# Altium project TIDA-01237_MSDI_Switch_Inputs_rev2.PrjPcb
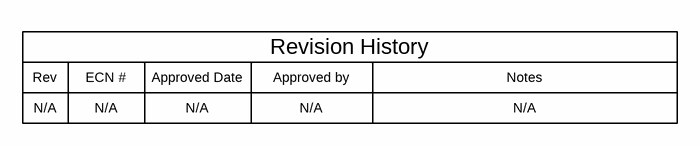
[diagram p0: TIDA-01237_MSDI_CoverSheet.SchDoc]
TID: TIDA-01237; TechSupport: http://www.ti.com/support; SCH_Rev: E2; PRJ_Title: MSDI Switch Inputs TI Design; PRJ_Number: TIDA-01237; PRJ_Engineer: John Griffith; PRJ_Customer: Public Release; PCB_Rev: E2; PCB_Layout: John Griffith; CopyrightYear: 2016
5 sheets, 162 parts. Net scope: global (net labels, ports and power ports of the same name join across sheets).
Board file: TIDA-01237_MSDI_Switch_Inputs_PCB_Rev2.PcbDoc
Sheets:
  TIDA-01237_MSDI_CoverSheet.SchDoc
  TIDA-01237_MSDI_Main.SchDoc
  TIDA-01237_MSDI_Matrix_Inputs.SchDoc
  TIDA-01237_MSDI_Resistor_Coded_Inputs.SchDoc
  TIDA-01237_MSDI_Hardware.SchDoc

## Sheet TIDA-01237_MSDI_CoverSheet.SchDoc
size 431 x 279 mm; Date: Not shown in title block; ApprovedBy: Not shown in title block; CheckedBy: Not shown in title block; Author: Not shown in title block; CompanyName: Not shown in title block; Engineer: Not shown in title block; Organization: Not shown in title block; Address1: Not shown in title block; Address2: Not shown in title block; Address3: Not shown in title block; Address4: Not shown in title block; DocumentNumber: 1; Revision: Use project parameter SCH_Rev; SheetNumber: 1; SheetTotal: 5; PageSetup: Record=PageOptions¦CenterHorizontal=True¦CenterVertical=True¦PrintScale=1.00¦XCorrection=1.00¦YCorrection=1.00¦PrintKind=0¦BorderSize=5000000¦LeftOffset=0¦BottomOffset=0¦Orientation=2¦PaperLength=1000¦PaperWidth=1000¦Scale=100¦PaperSource=15¦PrintQuality=600¦MediaType=1¦DitherType=10¦PaperKind=Letter¦PrintScaleMode=1

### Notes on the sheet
- Rev
- N/A
- ECN #
- Approved Date
- Approved by
- Revision History
- Notes

## Sheet TIDA-01237_MSDI_Main.SchDoc
size 431 x 279 mm; Date: Not shown in title block; ApprovedBy: Not shown in title block; CheckedBy: Not shown in title block; Author: Not shown in title block; CompanyName: Not shown in title block; DrawnBy: John Griffith; Engineer: Not shown in title block; Organization: Not shown in title block; Address1: Not shown in title block; Address2: Not shown in title block; Address3: Not shown in title block; Address4: Not shown in title block; DocumentNumber: 1; Revision: Use project parameter SCH_Rev; SheetNumber: 2; SheetTotal: 5; PageSetup: Record=PageOptions¦CenterHorizontal=True¦CenterVertical=True¦PrintScale=0.64¦XCorrection=1.00¦YCorrection=1.00¦PrintKind=0¦BorderSize=5000000¦LeftOffset=0¦BottomOffset=0¦Orientation=2¦PaperLength=1000¦PaperWidth=1000¦Scale=100¦PaperSource=15¦PrintQuality=600¦MediaType=1¦DitherType=10¦PrintScaleMode=1¦PaperKind=Letter
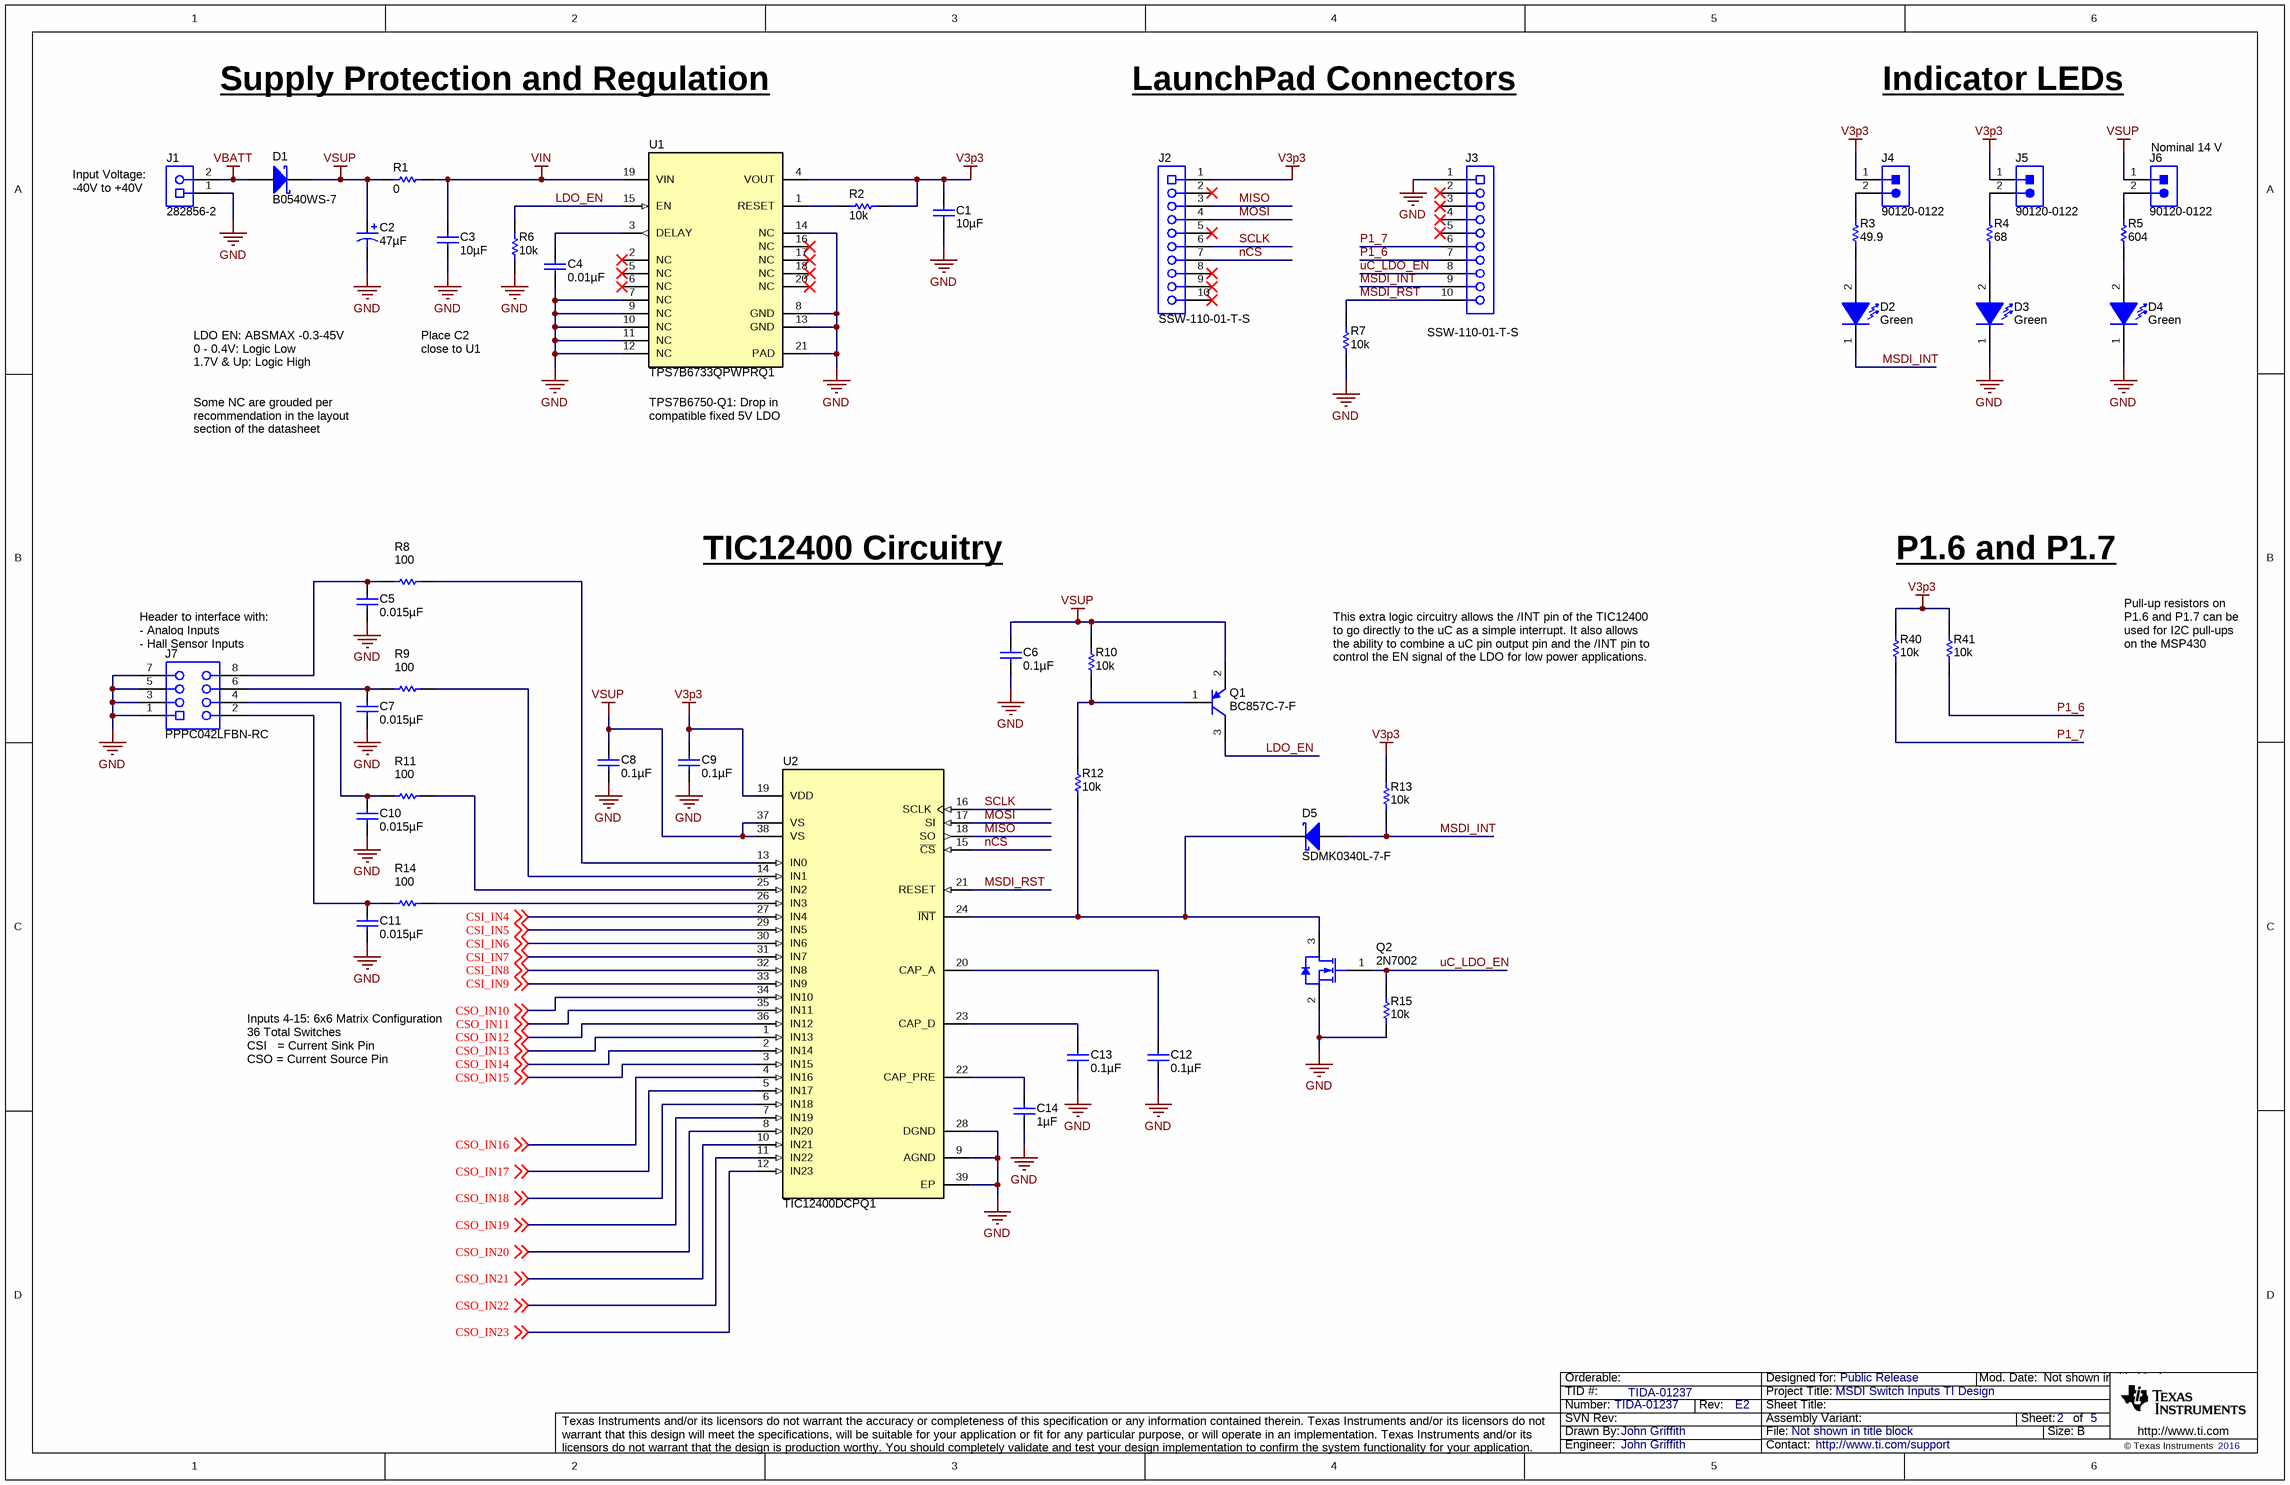
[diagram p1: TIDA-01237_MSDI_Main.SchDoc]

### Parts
C1  ValueDisplayed: 10µF  [0603S]  (hidden comment: C1608X5R1A106M080AC)
C2  ValueDisplayed: 47µF  [CAPSMT_62_F80]  (hidden comment: EMVE500ADA470MF80G)
C3  ValueDisplayed: 10µF  [1210_280]  (hidden comment: C3225X7R1H106M250AC)
C4  ValueDisplayed: 0.01µF  [0603S]  (hidden comment: C0603C103J5RACTU)
C5  ValueDisplayed: 0.015µF  [0603S]  (hidden comment: C0603C153J3GACTU)
C6  ValueDisplayed: 0.1µF  [0603S]  (hidden comment: 0603YC104JAT2A)
C7  ValueDisplayed: 0.015µF  [0603S]  (hidden comment: C0603C153J3GACTU)
C8  ValueDisplayed: 0.1µF  [0603S]  (hidden comment: 06035C104KAT2A)
C9  ValueDisplayed: 0.1µF  [0603S]  (hidden comment: 0603YC104JAT2A)
C10  ValueDisplayed: 0.015µF  [0603S]  (hidden comment: C0603C153J3GACTU)
C11  ValueDisplayed: 0.015µF  [0603S]  (hidden comment: C0603C153J3GACTU)
C12  ValueDisplayed: 0.1µF  [0603S]  (hidden comment: C1608X7R1E104K080AA)
C13  ValueDisplayed: 0.1µF  [0603S]  (hidden comment: C1608X7R1E104K080AA)
C14  ValueDisplayed: 1µF  [0603S]  (hidden comment: C1608X7R1C105K080AC)
D1  B0540WS-7  [SOD-323]
D2  value Green  [WL-SMCW_GREEN]  (hidden comment: 150060VS75000)
D3  value Green  [WL-SMCW_GREEN]  (hidden comment: 150060VS75000)
D4  value Green  [WL-SMCW_GREEN]  (hidden comment: 150060VS75000)
D5  SDMK0340L-7-F  [SOD-323]
J1  282856-2  [TE_282856-2]
J2  SSW-110-01-T-S  [Samtec_SSW-110-x1-x-S]
J3  SSW-110-01-T-S  [Samtec_SSW-110-x1-x-S]
J4  90120-0122  [CONN_90120-0122]
J5  90120-0122  [CONN_90120-0122]
J6  90120-0122  [CONN_90120-0122]
J7  PPPC042LFBN-RC  [CONN_PPPC042LFBN-RC]
Q1  BC857C-7-F  [SOT-23]
Q2  2N7002  [SOT-23]
R1  ValueDisplayed: 0  [5106]  (hidden comment: 5106)
R2  ValueDisplayed: 10k  [0603S]  (hidden comment: CRCW060310K0JNEA)
R3  ValueDisplayed: 49.9  [0402]  (hidden comment: ERJ-2RKF49R9X)
R4  ValueDisplayed: 68  [0402]  (hidden comment: CRCW040268R0JNED)
R5  ValueDisplayed: 604  [0402]  (hidden comment: CRCW0402604RFKED)
R6  ValueDisplayed: 10k  [0603S]  (hidden comment: CRCW060310K0JNEA)
R7  ValueDisplayed: 10k  [0603S]  (hidden comment: CRCW060310K0JNEA)
R8  ValueDisplayed: 100  [0603S]  (hidden comment: CRCW0603100RFKEA)
R9  ValueDisplayed: 100  [0603S]  (hidden comment: CRCW0603100RFKEA)
R10  ValueDisplayed: 10k  [0603S]  (hidden comment: CRCW060310K0JNEA)
R11  ValueDisplayed: 100  [0603S]  (hidden comment: CRCW0603100RFKEA)
R12  ValueDisplayed: 10k  [0603S]  (hidden comment: CRCW060310K0JNEA)
R13  ValueDisplayed: 10k  [0603S]  (hidden comment: CRCW060310K0JNEA)
R14  ValueDisplayed: 100  [0603S]  (hidden comment: CRCW0603100RFKEA)
R15  ValueDisplayed: 10k  [0603S]  (hidden comment: CRCW060310K0JNEA)
R40  ValueDisplayed: 10k  [0603S]  (hidden comment: RC0603JR-0710KL)
R41  ValueDisplayed: 10k  [0603S]  (hidden comment: RC0603JR-0710KL)
U1  TPS7B6733QPWPRQ1  [PWP0020D_N]
U2  TIC12400DCPQ1  [DCP0038A_N]

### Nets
GND: C1.2 C2.2(-) C3.2 C4.2 C5.2 C6.2 C7.2 C8.2 C9.2 C10.2 C11.2 C12.2 C13.2 C14.2 D3.1(K) D4.1(K) J1.1 J3.1 J7.1 J7.3 J7.5 J7.7 Q2.2(S) R6.1 R7.1 R15.2 U1.7(NC) U1.8(GND) U1.9(NC) U1.10(NC) U1.11(NC) U1.12(NC) U1.13(GND) U1.14(NC) U1.21(PAD) U2.9(AGND) U2.28(DGND) U2.39(EP)
V3p3: C1.1 C9.1 J2.1 J4.1 J5.1 R2.2 R13.2 R40.2 R41.2 U1.4(VOUT) U2.19(VDD)
VBATT: D1.2(A) J1.2
VIN: C3.1 R1.2 U1.19(VIN)
VSUP: C2.1(+) C6.1 C8.1 D1.1(K) J6.1 Q1.2(E) R1.1 R10.2 U2.37(VS) U2.38(VS)
CSI_IN4: U2.27(IN4) ; off-sheet CSI_IN4
CSI_IN5: U2.29(IN5) ; off-sheet CSI_IN5
CSI_IN6: U2.30(IN6) ; off-sheet CSI_IN6
CSI_IN7: U2.31(IN7) ; off-sheet CSI_IN7
CSI_IN8: U2.32(IN8) ; off-sheet CSI_IN8
CSI_IN9: U2.33(IN9) ; off-sheet CSI_IN9
CSO_IN10: U2.34(IN10) ; off-sheet CSO_IN10
CSO_IN11: U2.35(IN11) ; off-sheet CSO_IN11
CSO_IN12: U2.36(IN12) ; off-sheet CSO_IN12
CSO_IN13: U2.1(IN13) ; off-sheet CSO_IN13
CSO_IN14: U2.2(IN14) ; off-sheet CSO_IN14
CSO_IN15: U2.3(IN15) ; off-sheet CSO_IN15
CSO_IN16: U2.4(IN16) ; off-sheet CSO_IN16
CSO_IN17: U2.5(IN17) ; off-sheet CSO_IN17
CSO_IN18: U2.6(IN18) ; off-sheet CSO_IN18
CSO_IN19: U2.7(IN19) ; off-sheet CSO_IN19
CSO_IN20: U2.8(IN20) ; off-sheet CSO_IN20
CSO_IN21: U2.10(IN21) ; off-sheet CSO_IN21
CSO_IN22: U2.11(IN22) ; off-sheet CSO_IN22
CSO_IN23: U2.12(IN23) ; off-sheet CSO_IN23
LDO_EN: Q1.3(C) R6.2 U1.15(EN)
MISO: J2.3 U2.18(SO)
MOSI: J2.4 U2.17(SI)
MSDI_INT: D2.1(K) D5.2(A) J3.9 R13.1
MSDI_RST: J3.10 R7.2 U2.21(RESET)
nCS: J2.7 U2.15(~{CS})
P1_6: J3.7 R41.1
P1_7: J3.6 R40.1
SCLK: J2.6 U2.16(SCLK)
uC_LDO_EN: J3.8 Q2.1(G) R15.1
NetC4_1: C4.1 U1.3(DELAY)
NetC5_1: C5.1 J7.8 R8.1
NetC7_1: C7.1 J7.6 R9.1
NetC10_1: C10.1 J7.4 R11.1
NetC11_1: C11.1 J7.2 R14.1
NetC12_1: C12.1 U2.20(CAP_A)
NetC13_1: C13.1 U2.23(CAP_D)
NetC14_1: C14.1 U2.22(CAP_PRE)
NetD2_2: D2.2(A) R3.1
NetD3_2: D3.2(A) R4.1
NetD4_2: D4.2(A) R5.1
NetD5_1: D5.1(K) Q2.3(D) R12.2 U2.24(~{INT})
NetJ4_2: J4.2 R3.2
NetJ5_2: J5.2 R4.2
NetJ6_2: J6.2 R5.2
NetQ1_1: Q1.1(B) R10.1 R12.1
NetR2_1: R2.1 U1.1(RESET)
NetR8_2: R8.2 U2.13(IN0)
NetR9_2: R9.2 U2.14(IN1)
NetR11_2: R11.2 U2.25(IN2)
NetR14_2: R14.2 U2.26(IN3)

Not connected (* = marked no-connect by the designer): J2 2* 5* 8* 9* 10*; J3 2* 3* 4* 5*; U1 2(NC)* 5(NC)* 6(NC)* 16(NC)* 17(NC)* 18(NC)* 20(NC)*

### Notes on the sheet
- Supply Protection and Regulation
- LaunchPad Connectors
- Indicator LEDs
- (near J6) Nominal 14 V
- (near J1) Input Voltage:
  -40V to +40V
- LDO EN: ABSMAX -0.3-45V
  0 - 0.4V: Logic Low
  1.7V & Up: Logic High
- Place C2 close to U1
- Some NC are grouded per recommendation in the layout section of the datasheet
- (near U1) TPS7B6750-Q1: Drop in compatible fixed 5V LDO
- (near J7) - Analog Inputs
- Header to interface with:
- TIC12400 Circuitry
- P1.6 and P1.7
- (near J7) - Hall Sensor Inputs
- This extra logic circuitry allows the /INT pin of the TIC12400 to go directly to the uC as a simple interrupt. It also allows the ability to combine a uC pin output pin and the /INT pin to control the EN signal of the LDO for low power applications.
- Pull-up resistors on P1.6 and P1.7 can be used for I2C pull-ups on the MSP430
- Inputs 4-15: 6x6 Matrix Configuration
  36 Total Switches
  CSI   = Current Sink Pin
  CSO = Current Source Pin

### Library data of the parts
C1 = C1608X5R1A106M080AC: CAP, CERM, 10 µF, 10 V, +/- 20%, X5R, 0603; Manufacturer: TDK; Polarized: N; CompType: Capacitor; Value: 10uF; U/M: EA; Cap_F: 0.00001; Tolerance_%: 20; ESR_ohm: 0.0078; Value1: 0.0078 ohm; VDC_V: 10; Value2: 10V; IRMS_A: 1.85; TaMin_C: -55; TaMax_C: 85; Cap_Case: 0603; SizeArea_mm2: 1.28; SizeAreaWB_mm2: 4.68; SizeX_mm: 1.6; SizeY_mm: 0.8; SizeZ_mm: 1; AEC Category: Q200
C2 = EMVE500ADA470MF80G: CAP, AL, 47 µF, 50 V, +/- 20%, SMD; Manufacturer: Chemi-Con; Polarized: Y; CompType: Capacitor; Value: 47uF; U/M: EA; Cap_F: 0.000047; Tolerance_%: 20; Value1: Unknown; VDC_V: 50; Value2: 50V; IRMS_A: 0.08; TaMin_C: -40; TaMax_C: 105; Cap_Case: F80; SizeAreaWB_mm2: 73.96; SizeArea_mm2: 43.56; SizeX_mm: 6.6; SizeZ_mm: 7.7; AEC Category: Q200
C3 = C3225X7R1H106M250AC: CAP, CERM, 10 µF, 50 V, +/- 20%, X7R, 1210; Manufacturer: TDK; Polarized: N; CompType: Capacitor; Value: 10uF; U/M: EA; Cap_F: 0.00001; Tolerance_%: 20; Value1: Unknown; VDC_V: 50; Value2: 50V; TaMin_C: -55; TaMax_C: 125; Cap_Case: 1210; SizeArea_mm2: 8; SizeAreaWB_mm2: 14.7; SizeX_mm: 3.2; SizeY_mm: 2.5; SizeZ_mm: 2.8; AEC Category: Q200
C4 = C0603C103J5RACTU: CAP, CERM, 0.01 µF, 50 V, +/- 5%, X7R, 0603; Manufacturer: Kemet; Polarized: N; CompType: Capacitor; Value: 0.01uF; U/M: EA; Cap_F: 0.00000001; Tolerance_%: 5; Value1: Unknown; VDC_V: 50; Value2: 50V; TaMin_C: -55; TaMax_C: 125; Cap_Case: 0603; SizeArea_mm2: 1.28; SizeAreaWB_mm2: 4.68; SizeX_mm: 1.6; SizeY_mm: 0.8; SizeZ_mm: 1; AEC Category: Q200
C5 C7 C10 C11 = C0603C153J3GACTU: CAP, CERM, 0.015 µF, 25 V, +/- 5%, C0G/NP0, 0603; Manufacturer: Kemet; Polarized: N; CompType: Capacitor; Value: 0.015uF; U/M: EA; Cap_F: 0.000000015; Tolerance_%: 5; Value1: Unknown; VDC_V: 25; Value2: 25V; TaMin_C: -55; TaMax_C: 125; Cap_Case: 0603; SizeArea_mm2: 1.28; SizeAreaWB_mm2: 4.68; SizeX_mm: 1.6; SizeY_mm: 0.8; SizeZ_mm: 1; AEC Category: Q200
C6 C9 = 0603YC104JAT2A: CAP, CERM, 0.1 µF, 16 V, +/- 5%, X7R, 0603; Manufacturer: AVX; Polarized: N; CompType: Capacitor; Value: 0.1uF; U/M: EA; Cap_F: 0.0000001; Tolerance_%: 5; ESR_ohm: 0.039; Value1: 0.039 ohm; VDC_V: 16; Value2: 16V; TaMin_C: -55; TaMax_C: 125; Cap_Case: 0603; SizeArea_mm2: 1.28; SizeAreaWB_mm2: 4.68; SizeX_mm: 1.6; SizeY_mm: 0.8; SizeZ_mm: 1; AEC Category: Q200
C8 = 06035C104KAT2A: CAP, CERM, 0.1 µF, 50 V, +/- 10%, X7R, 0603; Manufacturer: AVX; Polarized: N; CompType: Capacitor; Value: 0.1uF; U/M: EA; Cap_F: 0.0000001; Tolerance_%: 10; Value1: Unknown; VDC_V: 50; Value2: 50V; TaMin_C: -55; TaMax_C: 125; Cap_Case: 0603; SizeArea_mm2: 1.28; SizeAreaWB_mm2: 4.68; SizeX_mm: 1.6; SizeY_mm: 0.8; SizeZ_mm: 1; AEC Category: Q200
C12 C13 = C1608X7R1E104K080AA: CAP, CERM, 0.1 µF, 25 V, +/- 10%, X7R, 0603; Manufacturer: TDK; Polarized: N; CompType: Capacitor; Value: 0.1uF; U/M: EA; Cap_F: 0.0000001; Tolerance_%: 10; Value1: Unknown; VDC_V: 25; Value2: 25V; TaMin_C: -55; TaMax_C: 125; Cap_Case: 0603; SizeArea_mm2: 1.28; SizeAreaWB_mm2: 4.68; SizeX_mm: 1.6; SizeY_mm: 0.8; SizeZ_mm: 1; AEC Category: Q200
C14 = C1608X7R1C105K080AC: CAP, CERM, 1 µF, 16 V, +/- 10%, X7R, 0603; Manufacturer: TDK; Polarized: N; CompType: Capacitor; Value: 1uF; U/M: EA; Cap_F: 0.000001; Tolerance_%: 10; ESR_ohm: 0.0057; Value1: 0.0057 ohm; VDC_V: 16; Value2: 16V; TaMin_C: -55; TaMax_C: 125; Cap_Case: 0603; SizeArea_mm2: 1.28; SizeAreaWB_mm2: 4.68; SizeX_mm: 1.6; SizeY_mm: 0.8; SizeZ_mm: 1; AEC Category: Q200
D1 = B0540WS-7: Diode, Schottky, 40 V, 0.5 A, SOD-323; Manufacturer: Diodes Inc.; U/M: EA; Vf_V: 0.55; Value: 40V; Value1: 0.5A; Value2: 0.55V; Io_A: 0.5; Vr_V: 40; TJmax_C: 125; SizeAreaWB_mm2: 8.695; SizeArea_mm2: 3.645; SizeX_mm: 2.7; SizeY_mm: 1.35; SizeZ_mm: 1; AEC Category: Q101
D2-D4 = 150060VS75000: LED, Green, SMD; Manufacturer: Wurth Elektronik; Type: AlInGaP; Vf_V: 2; Value2: 2V; Io_A: 0.02; Value1: W; U/M: EA
D5 = SDMK0340L-7-F: Diode, Schottky, 40 V, 0.03 A, SOD-323; Manufacturer: Diodes Inc.; U/M: EA; Vf_V: 1; Value: 40V; Value1: 0.03A; Value2: 1V; Io_A: 0.03; Vr_V: 40; SizeAreaWB_mm2: 8.695; SizeArea_mm2: 3.645; SizeX_mm: 2.7; SizeY_mm: 1.35; AEC Category: Q101
J1 = 282856-2: Therminal Block, 5 mm, 2-pole, Tin, TH; Manufacturer: TE Connectivity; SymbolCreator: a0412235; CompType: Terminal Block
J2 J3 = SSW-110-01-T-S: Receptacle, 2.54mm, 10x1, Tin, TH; Manufacturer: Samtec; SymbolCreator: a0411947; Pitch_mm: 2.54; Gender: Female; Row_Count: 1; Cert_CSA: Y
J4-J6 = 90120-0122: Header, 100mil, 2x1, Tin, TH; Manufacturer: Molex; SymbolCreator: a0412235
J7 = PPPC042LFBN-RC: Connector, Receptacle, 100mil, 4x2, Gold plated, TH; Manufacturer: Sullins Connector Solutions; SymbolCreator: a0412235
Q1 = BC857C-7-F, Diodes Inc.: Transistor, PNP, 45 V, 0.1 A, SOT-23; CompType: BJT; PNP: 1; NPN: 0; Vceo_V: 45; Vcesat1_V: 0.075; Value: 45 V; IcRated_A: 0.1; Value1: 0.1 A; HfeMax: 600; TaMin_C: -65; TaMax_C: 150; U/M: EA; AEC Category: Q101
Q2 = 2N7002: MOSFET, N-CH, 60 V, 115 A, SOT-23; Manufacturer: Fairchild Semiconductor; Alternate Manufacturer: None; U/M: EA; ChType: N; Value: 60V; VdsMax_V: 60; Value1: ? ohm; Value2: ? nC; Vgs_V: 20; IdsMax_A: 115; SizeAreaWB_mm2: 14; SizeArea_mm2: 7.5; SizeX_mm: 2.5; SizeY_mm: 3; SizeZ_mm: 1.1; AEC Category: Q101
R1 = 5106: RES, 0, 1%, 0.5 W, 0805; Manufacturer: Keystone; CompType: Resistor; Value: 0; Tolerance_%: 1; Power_W: 0.5; Value2: 0.5W; TempCo: ppm/C; SizeArea_mm2: 2.5; SizeX_mm: 2; SizeY_mm: 1.25; SizeZ_mm: 0.84; U/M: EA; AEC Category: Q200; AEC Qualified: N
R2 R6 R7 R10 R12 R13 R15 = CRCW060310K0JNEA: RES, 10 k, 5%, 0.1 W, 0603; Manufacturer: Vishay-Dale; CompType: Resistor; Value: 10k; Res_ohm: 10000; Value_Code: 10k0; Tolerance_%: 5; Power_W: 0.1; Value2: 0.1W; VDC_V: 75; TempCo: 200 ppm/C; SizeArea_mm2: 1.28; SizeX_mm: 1.6; SizeY_mm: 0.8; SizeZ_mm: 1; EIA_Code: E24; U/M: EA; AEC Category: Q200
R3 = ERJ-2RKF49R9X: RES, 49.9, 1%, 0.1 W, AEC-Q200 Grade 0, 0402; Manufacturer: Panasonic; CompType: Resistor; Value: 49.9; Value_Code: 49R9; Tolerance_%: 1; Power_W: 0.1; Value2: 0.1W; VDC_V: 50; TempCo: 100 ppm/C; SizeArea_mm2: 0.5; SizeZ_mm: 0.6; EIA_Code: E96; U/M: EA; AEC Category: Q200; AEC Qualified: Y; AEC Grade: 0
R4 = CRCW040268R0JNED: RES, 68, 5%, 0.063 W, 0402; Manufacturer: Vishay-Dale; CompType: Resistor; Value: 68; Value_Code: 68R0; Tolerance_%: 5; Power_W: 0.063; Value2: 0.063W; VDC_V: 50; TempCo: 200 ppm/C; SizeArea_mm2: 0.5; SizeX_mm: 1; SizeZ_mm: 0.6; EIA_Code: E24; U/M: EA; AEC Category: Q200
R5 = CRCW0402604RFKED: RES, 604, 1%, 0.063 W, 0402; Manufacturer: Vishay-Dale; CompType: Resistor; Value: 604; Value_Code: 604R; Tolerance_%: 1; Power_W: 0.063; Value2: 0.063W; VDC_V: 50; TempCo: 100 ppm/C; SizeArea_mm2: 0.5; SizeZ_mm: 0.6; EIA_Code: E96; U/M: EA; AEC Category: Q200
R8 R9 R11 R14 = CRCW0603100RFKEA: RES, 100, 1%, 0.1 W, 0603; Manufacturer: Vishay-Dale; CompType: Resistor; Value: 100; Value_Code: 100R; Tolerance_%: 1; Power_W: 0.1; Value2: 0.1W; VDC_V: 75; TempCo: 100 ppm/C; SizeArea_mm2: 1.28; SizeX_mm: 1.6; SizeY_mm: 0.8; EIA_Code: E96; U/M: EA; AEC Category: Q200
R40 R41 = RC0603JR-0710KL: RES, 10 k, 5%, 0.1 W, 0603; Manufacturer: Yageo America; CompType: Resistor; Value: 10k; Res_ohm: 10000; Value_Code: 10k0; Tolerance_%: 5; Power_W: 0.1; Value2: 0.1W; VDC_V: 50; TempCo: 100 ppm/C; SizeArea_mm2: 1.28; SizeX_mm: 1.6; SizeY_mm: 0.8; SizeZ_mm: 1; EIA_Code: E24; U/M: EA; AEC Category: Q200
U1 = TPS7B6733QPWPRQ1: 450-mA High-Voltage Ultra-Low IQ Low-Dropout Regulator, PWP0020D; Manufacturer: Texas Instruments; SymbolCreator: Altium; SizeArea_mm2: 41.6; SizeAreaWB_mm2: 71.4; SizeX_mm: 6.4; SizeY_mm: 6.5; SizeZ_mm: 1.2; CompType: IC; U/M: EA
U2 = TIC12400DCPQ1: Multiple Switch Detection Interface (MSDI) device, DCP0038A; Manufacturer: Texas Instruments; SymbolCreator: Altium; SizeArea_mm2: 62.08; SizeAreaWB_mm2: 98.28; SizeX_mm: 6.4; SizeY_mm: 9.7; SizeZ_mm: 1.2; CompType: IC; U/M: EA

## Sheet TIDA-01237_MSDI_Matrix_Inputs.SchDoc
size 431 x 279 mm; Date: Not shown in title block; ApprovedBy: Not shown in title block; CheckedBy: Not shown in title block; Author: Not shown in title block; CompanyName: Not shown in title block; Engineer: Not shown in title block; Organization: Not shown in title block; Address1: Not shown in title block; Address2: Not shown in title block; Address3: Not shown in title block; Address4: Not shown in title block; DocumentNumber: 1; Revision: Use project parameter SCH_Rev; SheetNumber: 3; SheetTotal: 5; PageSetup: Record=PageOptions¦CenterHorizontal=True¦CenterVertical=True¦PrintScale=1.00¦XCorrection=1.00¦YCorrection=1.00¦PrintKind=0¦BorderSize=5000000¦LeftOffset=0¦BottomOffset=0¦Orientation=2¦PaperLength=1000¦PaperWidth=1000¦Scale=100¦PaperSource=15¦PrintQuality=600¦MediaType=1¦DitherType=10¦PaperKind=Letter¦PrintScaleMode=1
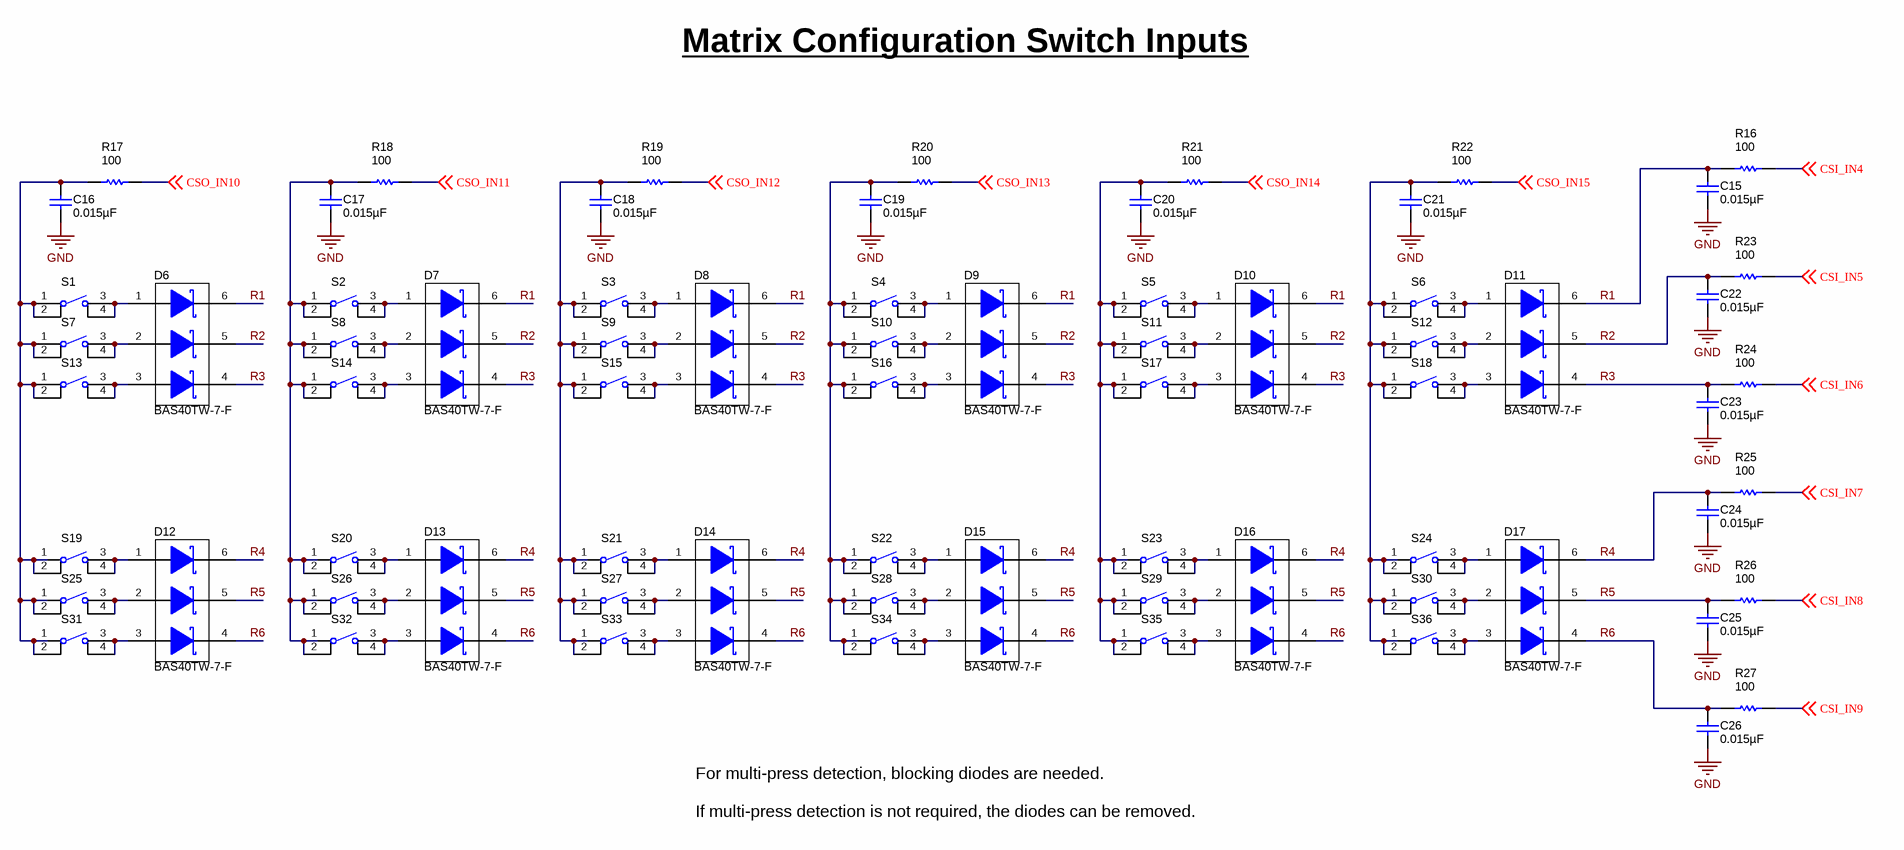
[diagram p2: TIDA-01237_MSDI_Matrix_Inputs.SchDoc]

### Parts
C15  ValueDisplayed: 0.015µF  [0603S]  (hidden comment: C0603C153J3GACTU)
C16  ValueDisplayed: 0.015µF  [0603S]  (hidden comment: C0603C153J3GACTU)
C17  ValueDisplayed: 0.015µF  [0603S]  (hidden comment: C0603C153J3GACTU)
C18  ValueDisplayed: 0.015µF  [0603S]  (hidden comment: C0603C153J3GACTU)
C19  ValueDisplayed: 0.015µF  [0603S]  (hidden comment: C0603C153J3GACTU)
C20  ValueDisplayed: 0.015µF  [0603S]  (hidden comment: C0603C153J3GACTU)
C21  ValueDisplayed: 0.015µF  [0603S]  (hidden comment: C0603C153J3GACTU)
C22  ValueDisplayed: 0.015µF  [0603S]  (hidden comment: C0603C153J3GACTU)
C23  ValueDisplayed: 0.015µF  [0603S]  (hidden comment: C0603C153J3GACTU)
C24  ValueDisplayed: 0.015µF  [0603S]  (hidden comment: C0603C153J3GACTU)
C25  ValueDisplayed: 0.015µF  [0603S]  (hidden comment: C0603C153J3GACTU)
C26  ValueDisplayed: 0.015µF  [0603S]  (hidden comment: C0603C153J3GACTU)
D6  BAS40TW-7-F  [SOT-363]
D7  BAS40TW-7-F  [SOT-363]
D8  BAS40TW-7-F  [SOT-363]
D9  BAS40TW-7-F  [SOT-363]
D10  BAS40TW-7-F  [SOT-363]
D11  BAS40TW-7-F  [SOT-363]
D12  BAS40TW-7-F  [SOT-363]
D13  BAS40TW-7-F  [SOT-363]
D14  BAS40TW-7-F  [SOT-363]
D15  BAS40TW-7-F  [SOT-363]
D16  BAS40TW-7-F  [SOT-363]
D17  BAS40TW-7-F  [SOT-363]
R16  ValueDisplayed: 100  [0603S]  (hidden comment: CRCW0603100RFKEA)
R17  ValueDisplayed: 100  [0603S]  (hidden comment: CRCW0603100RFKEA)
R18  ValueDisplayed: 100  [0603S]  (hidden comment: CRCW0603100RFKEA)
R19  ValueDisplayed: 100  [0603S]  (hidden comment: CRCW0603100RFKEA)
R20  ValueDisplayed: 100  [0603S]  (hidden comment: CRCW0603100RFKEA)
R21  ValueDisplayed: 100  [0603S]  (hidden comment: CRCW0603100RFKEA)
R22  ValueDisplayed: 100  [0603S]  (hidden comment: CRCW0603100RFKEA)
R23  ValueDisplayed: 100  [0603S]  (hidden comment: CRCW0603100RFKEA)
R24  ValueDisplayed: 100  [0603S]  (hidden comment: CRCW0603100RFKEA)
R25  ValueDisplayed: 100  [0603S]  (hidden comment: CRCW0603100RFKEA)
R26  ValueDisplayed: 100  [0603S]  (hidden comment: CRCW0603100RFKEA)
R27  ValueDisplayed: 100  [0603S]  (hidden comment: CRCW0603100RFKEA)
S1  4-1437565-1  [SW_FSM4JSMA]  (value not drawn)
S2  4-1437565-1  [SW_FSM4JSMA]  (value not drawn)
S3  4-1437565-1  [SW_FSM4JSMA]  (value not drawn)
S4  4-1437565-1  [SW_FSM4JSMA]  (value not drawn)
S5  4-1437565-1  [SW_FSM4JSMA]  (value not drawn)
S6  4-1437565-1  [SW_FSM4JSMA]  (value not drawn)
S7  4-1437565-1  [SW_FSM4JSMA]  (value not drawn)
S8  4-1437565-1  [SW_FSM4JSMA]  (value not drawn)
S9  4-1437565-1  [SW_FSM4JSMA]  (value not drawn)
S10  4-1437565-1  [SW_FSM4JSMA]  (value not drawn)
S11  4-1437565-1  [SW_FSM4JSMA]  (value not drawn)
S12  4-1437565-1  [SW_FSM4JSMA]  (value not drawn)
S13  4-1437565-1  [SW_FSM4JSMA]  (value not drawn)
S14  4-1437565-1  [SW_FSM4JSMA]  (value not drawn)
S15  4-1437565-1  [SW_FSM4JSMA]  (value not drawn)
S16  4-1437565-1  [SW_FSM4JSMA]  (value not drawn)
S17  4-1437565-1  [SW_FSM4JSMA]  (value not drawn)
S18  4-1437565-1  [SW_FSM4JSMA]  (value not drawn)
S19  4-1437565-1  [SW_FSM4JSMA]  (value not drawn)
S20  4-1437565-1  [SW_FSM4JSMA]  (value not drawn)
S21  4-1437565-1  [SW_FSM4JSMA]  (value not drawn)
S22  4-1437565-1  [SW_FSM4JSMA]  (value not drawn)
S23  4-1437565-1  [SW_FSM4JSMA]  (value not drawn)
S24  4-1437565-1  [SW_FSM4JSMA]  (value not drawn)
S25  4-1437565-1  [SW_FSM4JSMA]  (value not drawn)
S26  4-1437565-1  [SW_FSM4JSMA]  (value not drawn)
S27  4-1437565-1  [SW_FSM4JSMA]  (value not drawn)
S28  4-1437565-1  [SW_FSM4JSMA]  (value not drawn)
S29  4-1437565-1  [SW_FSM4JSMA]  (value not drawn)
S30  4-1437565-1  [SW_FSM4JSMA]  (value not drawn)
S31  4-1437565-1  [SW_FSM4JSMA]  (value not drawn)
S32  4-1437565-1  [SW_FSM4JSMA]  (value not drawn)
S33  4-1437565-1  [SW_FSM4JSMA]  (value not drawn)
S34  4-1437565-1  [SW_FSM4JSMA]  (value not drawn)
S35  4-1437565-1  [SW_FSM4JSMA]  (value not drawn)
S36  4-1437565-1  [SW_FSM4JSMA]  (value not drawn)

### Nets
GND: C15.2 C16.2 C17.2 C18.2 C19.2 C20.2 C21.2 C22.2 C23.2 C24.2 C25.2 C26.2
CSI_IN4: R16.2 ; off-sheet CSI_IN4
CSI_IN5: R23.2 ; off-sheet CSI_IN5
CSI_IN6: R24.2 ; off-sheet CSI_IN6
CSI_IN7: R25.2 ; off-sheet CSI_IN7
CSI_IN8: R26.2 ; off-sheet CSI_IN8
CSI_IN9: R27.2 ; off-sheet CSI_IN9
CSO_IN10: R17.2 ; off-sheet CSO_IN10
CSO_IN11: R18.2 ; off-sheet CSO_IN11
CSO_IN12: R19.2 ; off-sheet CSO_IN12
CSO_IN13: R20.2 ; off-sheet CSO_IN13
CSO_IN14: R21.2 ; off-sheet CSO_IN14
CSO_IN15: R22.2 ; off-sheet CSO_IN15
R1: C15.1 D6.6(C) D7.6(C) D8.6(C) D9.6(C) D10.6(C) D11.6(C) R16.1
R2: C22.1 D6.5(NC) D7.5(NC) D8.5(NC) D9.5(NC) D10.5(NC) D11.5(NC) R23.1
R3: C23.1 D6.4(C) D7.4(C) D8.4(C) D9.4(C) D10.4(C) D11.4(C) R24.1
R4: C24.1 D12.6(C) D13.6(C) D14.6(C) D15.6(C) D16.6(C) D17.6(C) R25.1
R5: C25.1 D12.5(NC) D13.5(NC) D14.5(NC) D15.5(NC) D16.5(NC) D17.5(NC) R26.1
R6: C26.1 D12.4(C) D13.4(C) D14.4(C) D15.4(C) D16.4(C) D17.4(C) R27.1
NetC16_1: C16.1 R17.1 S1.1 S1.2 S7.1 S7.2 S13.1 S13.2 S19.1 S19.2 S25.1 S25.2 S31.1 S31.2
NetC17_1: C17.1 R18.1 S2.1 S2.2 S8.1 S8.2 S14.1 S14.2 S20.1 S20.2 S26.1 S26.2 S32.1 S32.2
NetC18_1: C18.1 R19.1 S3.1 S3.2 S9.1 S9.2 S15.1 S15.2 S21.1 S21.2 S27.1 S27.2 S33.1 S33.2
NetC19_1: C19.1 R20.1 S4.1 S4.2 S10.1 S10.2 S16.1 S16.2 S22.1 S22.2 S28.1 S28.2 S34.1 S34.2
NetC20_1: C20.1 R21.1 S5.1 S5.2 S11.1 S11.2 S17.1 S17.2 S23.1 S23.2 S29.1 S29.2 S35.1 S35.2
NetC21_1: C21.1 R22.1 S6.1 S6.2 S12.1 S12.2 S18.1 S18.2 S24.1 S24.2 S30.1 S30.2 S36.1 S36.2
NetD6_1: D6.1(A) S1.3 S1.4
NetD6_2: D6.2(NC) S7.3 S7.4
NetD6_3: D6.3(A) S13.3 S13.4
NetD7_1: D7.1(A) S2.3 S2.4
NetD7_2: D7.2(NC) S8.3 S8.4
NetD7_3: D7.3(A) S14.3 S14.4
NetD8_1: D8.1(A) S3.3 S3.4
NetD8_2: D8.2(NC) S9.3 S9.4
NetD8_3: D8.3(A) S15.3 S15.4
NetD9_1: D9.1(A) S4.3 S4.4
NetD9_2: D9.2(NC) S10.3 S10.4
NetD9_3: D9.3(A) S16.3 S16.4
NetD10_1: D10.1(A) S5.3 S5.4
NetD10_2: D10.2(NC) S11.3 S11.4
NetD10_3: D10.3(A) S17.3 S17.4
NetD11_1: D11.1(A) S6.3 S6.4
NetD11_2: D11.2(NC) S12.3 S12.4
NetD11_3: D11.3(A) S18.3 S18.4
NetD12_1: D12.1(A) S19.3 S19.4
NetD12_2: D12.2(NC) S25.3 S25.4
NetD12_3: D12.3(A) S31.3 S31.4
NetD13_1: D13.1(A) S20.3 S20.4
NetD13_2: D13.2(NC) S26.3 S26.4
NetD13_3: D13.3(A) S32.3 S32.4
NetD14_1: D14.1(A) S21.3 S21.4
NetD14_2: D14.2(NC) S27.3 S27.4
NetD14_3: D14.3(A) S33.3 S33.4
NetD15_1: D15.1(A) S22.3 S22.4
NetD15_2: D15.2(NC) S28.3 S28.4
NetD15_3: D15.3(A) S34.3 S34.4
NetD16_1: D16.1(A) S23.3 S23.4
NetD16_2: D16.2(NC) S29.3 S29.4
NetD16_3: D16.3(A) S35.3 S35.4
NetD17_1: D17.1(A) S24.3 S24.4
NetD17_2: D17.2(NC) S30.3 S30.4
NetD17_3: D17.3(A) S36.3 S36.4

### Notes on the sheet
- Matrix Configuration Switch Inputs
- For multi-press detection, blocking diodes are needed.
  If multi-press detection is not required, the diodes can be removed.

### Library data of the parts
C15-C26 = C0603C153J3GACTU: as C5 on sheet TIDA-01237_MSDI_Main
D6-D17 = BAS40TW-7-F: Diode, Schottky, 40 V, 0.2 A, AEC-Q101, SOT-363; Manufacturer: Diodes Inc.; SymbolCreator: Altium; U/M: EA; Vf_V: 1; Value: 40V; Value1: 0.2A; Value2: 1V; Io_A: 0.2; Vr_V: 40; TJmax_C: 125; SizeAreaWB_mm2: 10.24; SizeArea_mm2: 4.84; SizeX_mm: 2.2; SizeZ_mm: 1.1; AEC Category: Q101; AEC Qualified: Y
R16-R27 = CRCW0603100RFKEA: as R8 on sheet TIDA-01237_MSDI_Main
S1-S36 = 4-1437565-1: Switch, Tactile, SPST-NO, 0.05A, 12V, SMT; Manufacturer: TE Connectivity; SymbolCreator: a0412235; VDC_V: 12; SwitchFunction: Off-Mom; PositionCount: 1; CurrentRating_mA: 50

## Sheet TIDA-01237_MSDI_Resistor_Coded_Inputs.SchDoc
size 431 x 279 mm; Date: Not shown in title block; ApprovedBy: Not shown in title block; CheckedBy: Not shown in title block; Author: Not shown in title block; CompanyName: Not shown in title block; Engineer: Not shown in title block; Organization: Not shown in title block; Address1: Not shown in title block; Address2: Not shown in title block; Address3: Not shown in title block; Address4: Not shown in title block; DocumentNumber: 1; Revision: Use project parameter SCH_Rev; SheetNumber: 4; SheetTotal: 5; PageSetup: Record=PageOptions¦CenterHorizontal=True¦CenterVertical=True¦PrintScale=1.00¦XCorrection=1.00¦YCorrection=1.00¦PrintKind=0¦BorderSize=5000000¦LeftOffset=0¦BottomOffset=0¦Orientation=2¦PaperLength=1000¦PaperWidth=1000¦Scale=100¦PaperSource=15¦PrintQuality=600¦MediaType=1¦DitherType=10¦PaperKind=Letter¦PrintScaleMode=1
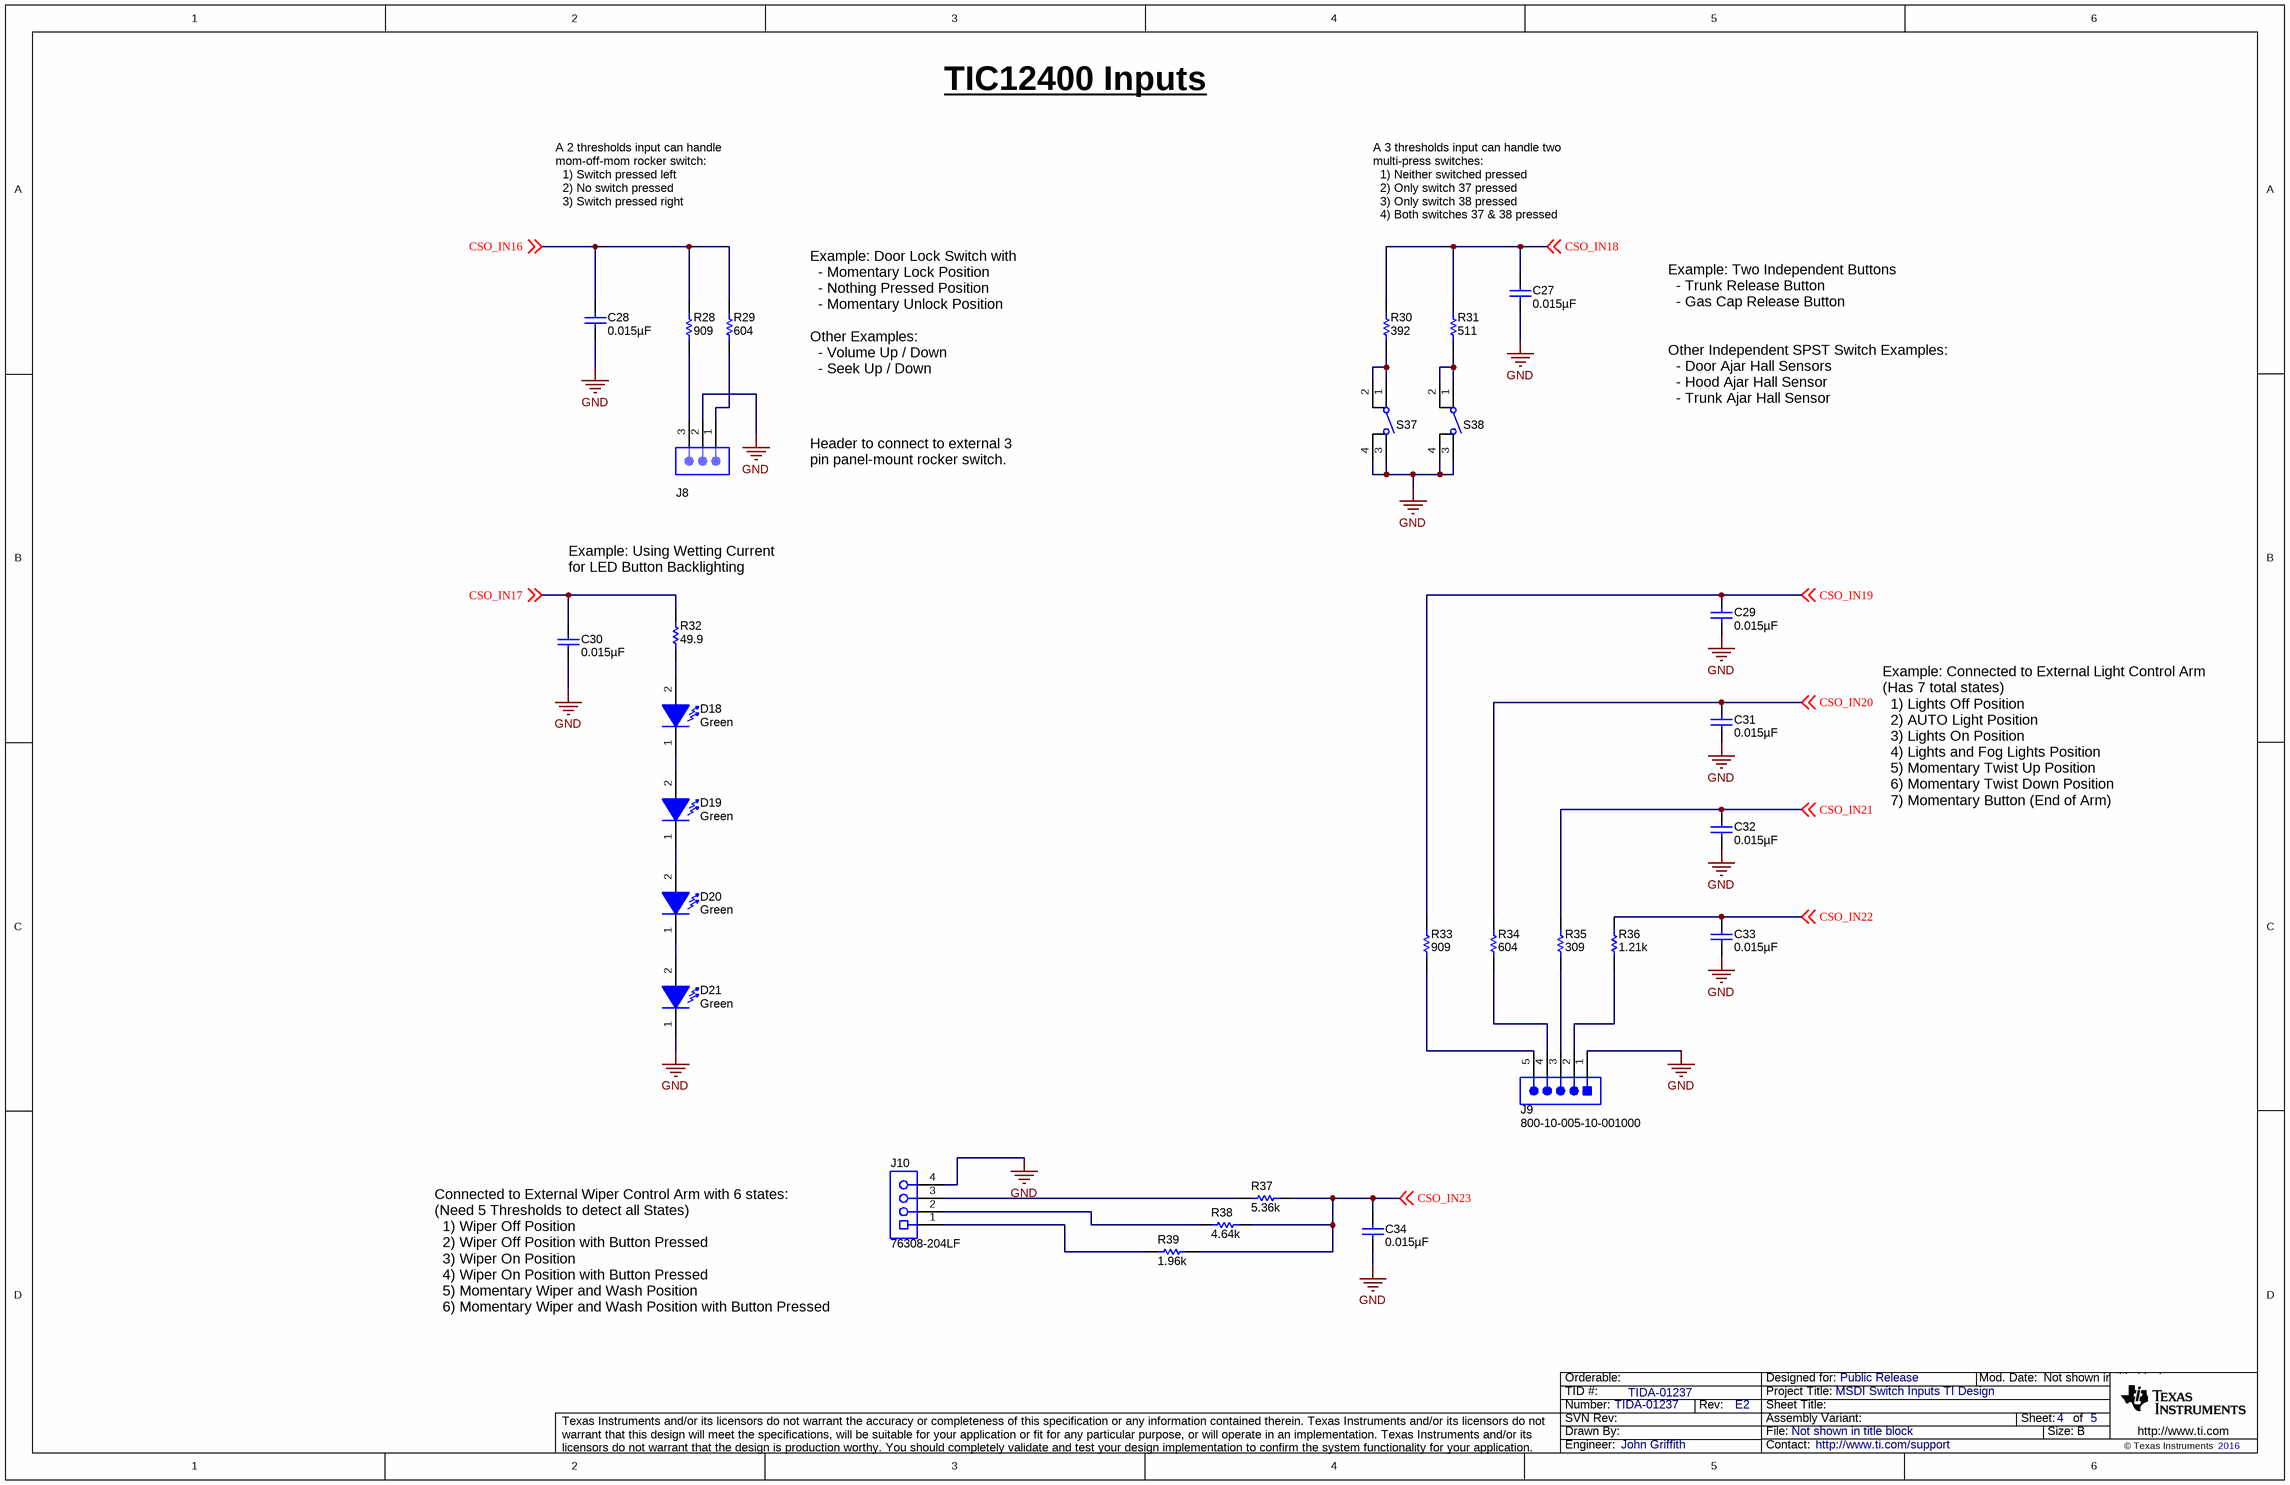
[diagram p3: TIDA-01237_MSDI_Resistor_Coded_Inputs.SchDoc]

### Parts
C27  ValueDisplayed: 0.015µF  [0603S]  (hidden comment: C0603C153J3GACTU)
C28  ValueDisplayed: 0.015µF  [0603S]  (hidden comment: C0603C153J3GACTU)
C29  ValueDisplayed: 0.015µF  [0603S]  (hidden comment: C0603C153J3GACTU)
C30  ValueDisplayed: 0.015µF  [0603S]  (hidden comment: C0603C153J3GACTU)
C31  ValueDisplayed: 0.015µF  [0603S]  (hidden comment: C0603C153J3GACTU)
C32  ValueDisplayed: 0.015µF  [0603S]  (hidden comment: C0603C153J3GACTU)
C33  ValueDisplayed: 0.015µF  [0603S]  (hidden comment: C0603C153J3GACTU)
C34  ValueDisplayed: 0.015µF  [0603S]  (hidden comment: C0603C153J3GACTU)
D18  value Green  [WL-SMCW_GREEN]  (hidden comment: 150060VS75000)
D19  value Green  [WL-SMCW_GREEN]  (hidden comment: 150060VS75000)
D20  value Green  [WL-SMCW_GREEN]  (hidden comment: 150060VS75000)
D21  value Green  [WL-SMCW_GREEN]  (hidden comment: 150060VS75000)
J8  PBC03SAAN  [PBC03SAAN]  (value not drawn)
J9  800-10-005-10-001000  [Mill-Max_800-10-005-10-001000]
J10  76308-204LF  [FCI_76308-204LF]
R28  ValueDisplayed: 909  [0603S]  (hidden comment: CRCW0603909RFKEA)
R29  ValueDisplayed: 604  [0603S]  (hidden comment: CRCW0603604RFKEA)
R30  ValueDisplayed: 392  [0603S]  (hidden comment: CRCW0603392RFKEA)
R31  ValueDisplayed: 511  [0603S]  (hidden comment: CRCW0603511RFKEA)
R32  ValueDisplayed: 49.9  [0603S]  (hidden comment: CRCW060349R9FKEA)
R33  ValueDisplayed: 909  [0603S]  (hidden comment: CRCW0603909RFKEA)
R34  ValueDisplayed: 604  [0603S]  (hidden comment: CRCW0603604RFKEA)
R35  ValueDisplayed: 309  [0603S]  (hidden comment: CRCW0603309RFKEA)
R36  ValueDisplayed: 1.21k  [0603S]  (hidden comment: CRCW06031K21FKEA)
R37  ValueDisplayed: 5.36k  [0603S]  (hidden comment: CRCW06035K36FKEA)
R38  ValueDisplayed: 4.64k  [0603S]  (hidden comment: CRCW06034K64FKEA)
R39  ValueDisplayed: 1.96k  [0603S]  (hidden comment: CRCW06031K96FKEA)
S37  4-1437565-1  [SW_FSM4JSMA]  (value not drawn)
S38  4-1437565-1  [SW_FSM4JSMA]  (value not drawn)

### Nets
GND: C27.2 C28.2 C29.2 C30.2 C31.2 C32.2 C33.2 C34.2 D21.1(K) J8.2 J9.1 J10.4 S37.3 S37.4 S38.3 S38.4
CSO_IN16: C28.1 R28.2 R29.2 ; off-sheet CSO_IN16
CSO_IN17: C30.1 R32.2 ; off-sheet CSO_IN17
CSO_IN18: C27.1 R30.2 R31.2 ; off-sheet CSO_IN18
CSO_IN19: C29.1 R33.2 ; off-sheet CSO_IN19
CSO_IN20: C31.1 R34.2 ; off-sheet CSO_IN20
CSO_IN21: C32.1 R35.2 ; off-sheet CSO_IN21
CSO_IN22: C33.1 R36.2 ; off-sheet CSO_IN22
CSO_IN23: C34.1 R37.2 R38.2 R39.2 ; off-sheet CSO_IN23
NetD18_1: D18.1(K) D19.2(A)
NetD18_2: D18.2(A) R32.1
NetD19_1: D19.1(K) D20.2(A)
NetD20_1: D20.1(K) D21.2(A)
NetJ8_1: J8.1 R29.1
NetJ8_3: J8.3 R28.1
NetJ9_2: J9.2 R36.1
NetJ9_3: J9.3 R35.1
NetJ9_4: J9.4 R34.1
NetJ9_5: J9.5 R33.1
NetJ10_1: J10.1 R39.1
NetJ10_2: J10.2 R38.1
NetJ10_3: J10.3 R37.1
NetR30_1: R30.1 S37.1 S37.2
NetR31_1: R31.1 S38.1 S38.2

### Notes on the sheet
- TIC12400 Inputs
- A 2 thresholds input can handle mom-off-mom rocker switch:
  1) Switch pressed left
  2) No switch pressed
  3) Switch pressed right
- A 3 thresholds input can handle two multi-press switches:
  1) Neither switched pressed
  2) Only switch 37 pressed
  3) Only switch 38 pressed
  4) Both switches 37 & 38 pressed
- Example: Two Independent Buttons
  - Trunk Release Button
  - Gas Cap Release Button
- Example: Door Lock Switch with
  - Momentary Lock Position
  - Nothing Pressed Position
  - Momentary Unlock Position
  Other Examples:
  - Volume Up / Down
  - Seek Up / Down
- Other Independent SPST Switch Examples:
  - Door Ajar Hall Sensors
  - Hood Ajar Hall Sensor
  - Trunk Ajar Hall Sensor
- Header to connect to external 3 pin panel-mount rocker switch.
- Example: Using Wetting Current for LED Button Backlighting
- Example: Connected to External Light Control Arm
  (Has 7 total states)
  1) Lights Off Position
  2) AUTO Light Position
  3) Lights On Position
  4) Lights and Fog Lights Position
  5) Momentary Twist Up Position
  6) Momentary Twist Down Position
  7) Momentary Button (End of Arm)
- Connected to External Wiper Control Arm with 6 states:
  (Need 5 Thresholds to detect all States)
  1) Wiper Off Position
  2) Wiper Off Position with Button Pressed
  3) Wiper On Position
  4) Wiper On Position with Button Pressed
  5) Momentary Wiper and Wash Position
  6) Momentary Wiper and Wash Position with Button Pressed

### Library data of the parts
C27-C34 = C0603C153J3GACTU: as C5 on sheet TIDA-01237_MSDI_Main
D18-D21 = 150060VS75000: as D2 on sheet TIDA-01237_MSDI_Main
J8 = PBC03SAAN: Header, 100mil, 3x1, Gold, TH; Manufacturer: Sullins Connector Solutions
J9 = 800-10-005-10-001000: Header, 100mil, 5x1, TH; Manufacturer: Mill-Max; SymbolCreator: a0412235
J10 = 76308-204LF: Receptacle, 100mil, 4x1, Gold, TH; Manufacturer: FCI; SymbolCreator: a0411947
R28 R33 = CRCW0603909RFKEA: RES, 909, 1%, 0.1 W, 0603; Manufacturer: Vishay-Dale; CompType: Resistor; Value: 909; Value_Code: 909R; Tolerance_%: 1; Power_W: 0.1; Value2: 0.1W; VDC_V: 75; TempCo: 100 ppm/C; SizeArea_mm2: 1.28; SizeX_mm: 1.6; SizeY_mm: 0.8; EIA_Code: E96; U/M: EA; AEC Category: Q200
R29 R34 = CRCW0603604RFKEA: RES, 604, 1%, 0.1 W, 0603; Manufacturer: Vishay-Dale; CompType: Resistor; Value: 604; Value_Code: 604R; Tolerance_%: 1; Power_W: 0.1; Value2: 0.1W; VDC_V: 75; TempCo: 100 ppm/C; SizeArea_mm2: 1.28; SizeX_mm: 1.6; SizeY_mm: 0.8; EIA_Code: E96; U/M: EA; AEC Category: Q200
R30 = CRCW0603392RFKEA: RES, 392, 1%, 0.1 W, 0603; Manufacturer: Vishay-Dale; CompType: Resistor; Value: 392; Value_Code: 392R; Tolerance_%: 1; Power_W: 0.1; Value2: 0.1W; VDC_V: 75; TempCo: 100 ppm/C; SizeArea_mm2: 1.28; SizeX_mm: 1.6; SizeY_mm: 0.8; EIA_Code: E96; U/M: EA; AEC Category: Q200
R31 = CRCW0603511RFKEA: RES, 511, 1%, 0.1 W, 0603; Manufacturer: Vishay-Dale; CompType: Resistor; Value: 511; Value_Code: 511R; Tolerance_%: 1; Power_W: 0.1; Value2: 0.1W; VDC_V: 75; TempCo: 100 ppm/C; SizeArea_mm2: 1.28; SizeX_mm: 1.6; SizeY_mm: 0.8; EIA_Code: E96; U/M: EA; AEC Category: Q200
R32 = CRCW060349R9FKEA: RES, 49.9, 1%, 0.1 W, 0603; Manufacturer: Vishay-Dale; CompType: Resistor; Value: 49.9; Value_Code: 49R9; Tolerance_%: 1; Power_W: 0.1; Value2: 0.1W; VDC_V: 75; TempCo: 100 ppm/C; SizeArea_mm2: 1.28; SizeX_mm: 1.6; SizeY_mm: 0.8; EIA_Code: E96; U/M: EA; AEC Category: Q200
R35 = CRCW0603309RFKEA: RES, 309, 1%, 0.1 W, 0603; Manufacturer: Vishay-Dale; CompType: Resistor; Value: 309; Value_Code: 309R; Tolerance_%: 1; Power_W: 0.1; Value2: 0.1W; VDC_V: 75; TempCo: 100 ppm/C; SizeArea_mm2: 1.28; SizeX_mm: 1.6; SizeY_mm: 0.8; EIA_Code: E96; U/M: EA; AEC Category: Q200
R36 = CRCW06031K21FKEA: RES, 1.21 k, 1%, 0.1 W, 0603; Manufacturer: Vishay-Dale; CompType: Resistor; Value: 1.21k; Res_ohm: 1210; Value_Code: 1k21; Tolerance_%: 1; Power_W: 0.1; Value2: 0.1W; VDC_V: 75; TempCo: 100 ppm/C; SizeArea_mm2: 1.28; SizeX_mm: 1.6; SizeY_mm: 0.8; EIA_Code: E96; U/M: EA; AEC Category: Q200
R37 = CRCW06035K36FKEA: RES, 5.36 k, 1%, 0.1 W, 0603; Manufacturer: Vishay-Dale; CompType: Resistor; Value: 5.36k; Res_ohm: 5360; Value_Code: 5k36; Tolerance_%: 1; Power_W: 0.1; Value2: 0.1W; VDC_V: 75; TempCo: 100 ppm/C; SizeArea_mm2: 1.28; SizeX_mm: 1.6; SizeY_mm: 0.8; EIA_Code: E96; U/M: EA; AEC Category: Q200
R38 = CRCW06034K64FKEA: RES, 4.64 k, 1%, 0.1 W, 0603; Manufacturer: Vishay-Dale; CompType: Resistor; Value: 4.64k; Res_ohm: 4640; Value_Code: 4k64; Tolerance_%: 1; Power_W: 0.1; Value2: 0.1W; VDC_V: 75; TempCo: 100 ppm/C; SizeArea_mm2: 1.28; SizeX_mm: 1.6; SizeY_mm: 0.8; EIA_Code: E96; U/M: EA; AEC Category: Q200
R39 = CRCW06031K96FKEA: RES, 1.96 k, 1%, 0.1 W, 0603; Manufacturer: Vishay-Dale; CompType: Resistor; Value: 1.96k; Res_ohm: 1960; Value_Code: 1k96; Tolerance_%: 1; Power_W: 0.1; Value2: 0.1W; VDC_V: 75; TempCo: 100 ppm/C; SizeArea_mm2: 1.28; SizeX_mm: 1.6; SizeY_mm: 0.8; EIA_Code: E96; U/M: EA; AEC Category: Q200
S37 S38 = 4-1437565-1: as S1 on sheet TIDA-01237_MSDI_Matrix_Inputs

## Sheet TIDA-01237_MSDI_Hardware.SchDoc
size 431 x 279 mm; Date: Not shown in title block; ApprovedBy: Not shown in title block; CheckedBy: Not shown in title block; Author: Not shown in title block; CompanyName: Not shown in title block; Engineer: Not shown in title block; Organization: Not shown in title block; Address1: Not shown in title block; Address2: Not shown in title block; Address3: Not shown in title block; Address4: Not shown in title block; DocumentNumber: 1; Revision: Use project parameter SCH_Rev; SheetNumber: 5; SheetTotal: 5; PageSetup: Record=PageOptions¦CenterHorizontal=True¦CenterVertical=True¦PrintScale=1.00¦XCorrection=1.00¦YCorrection=1.00¦PrintKind=0¦BorderSize=5000000¦LeftOffset=0¦BottomOffset=0¦Orientation=2¦PaperLength=1000¦PaperWidth=1000¦Scale=100¦PaperSource=15¦PrintQuality=600¦MediaType=1¦DitherType=10¦PaperKind=Letter¦PrintScaleMode=1
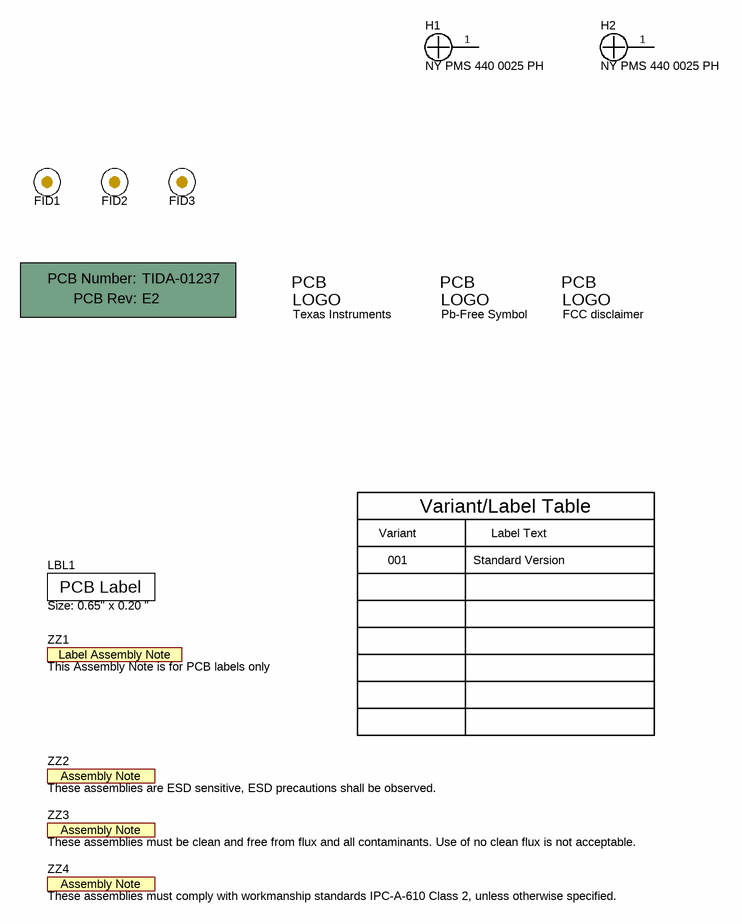
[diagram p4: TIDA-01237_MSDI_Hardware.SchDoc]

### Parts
!PCB1  Printed Circuit Board  (value not drawn)  (mechanical)
FID1  Fiducial  [Fiducial10-20]  (value not drawn)
FID2  Fiducial  [Fiducial10-20]  (value not drawn)
FID3  Fiducial  [Fiducial10-20]  (value not drawn)
H1  NY PMS 440 0025 PH  [NY PMS 440 0025 PH]
H2  NY PMS 440 0025 PH  [NY PMS 440 0025 PH]
LBL1  Size: 0.65" x 0.20 "  [Label_650x200]
Logo1  Texas Instruments  [TI_Stacked_Overlay_Small]  (no BOM)
Logo2  Pb-Free Symbol  [Pb-Free_Overlay_Small]  (no BOM)
Logo3  FCC disclaimer  [FCC_disclaimer]  (no BOM)
ZZ1  This Assembly Note is for PCB labels only  [AssemblyNoteLabel]  (no BOM)
ZZ2  These assemblies are ESD sensitive, ESD precautions shall be observed.  [AssemblyNote]  (no BOM)
ZZ3  These assemblies must be clean and free from flux and all contaminants. Use of no clean flux is not acceptable.  [AssemblyNote]  (no BOM)
ZZ4  These assemblies must comply with workmanship standards IPC-A-610 Class 2, unless otherwise specified.  [AssemblyNote]  (no BOM)

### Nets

Not connected (* = marked no-connect by the designer): H1 1; H2 1

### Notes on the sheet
- Variant
- Variant/Label Table
- Label Text
- 001
- Standard Version

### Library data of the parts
!PCB1 = PCB: Manufacturer: Any; PartNumber: TIDA-01237; SymbolCreator: a0412235
FID1-FID3 = Fiducial: Fiducial mark.  There is nothing to buy or mount.; SymbolCreator: codlsc
H1 H2 = NY PMS 440 0025 PH: Machine Screw, Round, #4-40 x 1/4, Nylon, Philips panhead; Manufacturer: B&F Fastener Supply; CompType: Hardware; SymbolCreator: codlsc; U/M: EA
LBL1 = THT-14-423-10: Thermal Transfer Printable Labels, 0.650" W x 0.200" H - 10,000 per roll; Manufacturer: Brady; SymbolCreator: a0412235; CompType: Label
Logo1 = TI_Logo: Texas Instrument Corporate Signature; SymbolCreator: codlsc
Logo2 = Pb-Free: SymbolCreator: a0412235
Logo3 = FCC_disclaimer: SymbolCreator: codlsc
ZZ1 = AssemblyNoteLabel: SymbolCreator: a0412235
ZZ2-ZZ4 = AssemblyNote: SymbolCreator: codlsc

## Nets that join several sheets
GND: TIDA-01237_MSDI_Main (38 pins), TIDA-01237_MSDI_Matrix_Inputs (12 pins), TIDA-01237_MSDI_Resistor_Coded_Inputs (16 pins)
CSI_IN4: TIDA-01237_MSDI_Main (U2.27), TIDA-01237_MSDI_Matrix_Inputs (R16.2)
CSI_IN5: TIDA-01237_MSDI_Main (U2.29), TIDA-01237_MSDI_Matrix_Inputs (R23.2)
CSI_IN6: TIDA-01237_MSDI_Main (U2.30), TIDA-01237_MSDI_Matrix_Inputs (R24.2)
CSI_IN7: TIDA-01237_MSDI_Main (U2.31), TIDA-01237_MSDI_Matrix_Inputs (R25.2)
CSI_IN8: TIDA-01237_MSDI_Main (U2.32), TIDA-01237_MSDI_Matrix_Inputs (R26.2)
CSI_IN9: TIDA-01237_MSDI_Main (U2.33), TIDA-01237_MSDI_Matrix_Inputs (R27.2)
CSO_IN10: TIDA-01237_MSDI_Main (U2.34), TIDA-01237_MSDI_Matrix_Inputs (R17.2)
CSO_IN11: TIDA-01237_MSDI_Main (U2.35), TIDA-01237_MSDI_Matrix_Inputs (R18.2)
CSO_IN12: TIDA-01237_MSDI_Main (U2.36), TIDA-01237_MSDI_Matrix_Inputs (R19.2)
CSO_IN13: TIDA-01237_MSDI_Main (U2.1), TIDA-01237_MSDI_Matrix_Inputs (R20.2)
CSO_IN14: TIDA-01237_MSDI_Main (U2.2), TIDA-01237_MSDI_Matrix_Inputs (R21.2)
CSO_IN15: TIDA-01237_MSDI_Main (U2.3), TIDA-01237_MSDI_Matrix_Inputs (R22.2)
CSO_IN16: TIDA-01237_MSDI_Main (U2.4), TIDA-01237_MSDI_Resistor_Coded_Inputs (C28.1 R28.2 R29.2)
CSO_IN17: TIDA-01237_MSDI_Main (U2.5), TIDA-01237_MSDI_Resistor_Coded_Inputs (C30.1 R32.2)
CSO_IN18: TIDA-01237_MSDI_Main (U2.6), TIDA-01237_MSDI_Resistor_Coded_Inputs (C27.1 R30.2 R31.2)
CSO_IN19: TIDA-01237_MSDI_Main (U2.7), TIDA-01237_MSDI_Resistor_Coded_Inputs (C29.1 R33.2)
CSO_IN20: TIDA-01237_MSDI_Main (U2.8), TIDA-01237_MSDI_Resistor_Coded_Inputs (C31.1 R34.2)
CSO_IN21: TIDA-01237_MSDI_Main (U2.10), TIDA-01237_MSDI_Resistor_Coded_Inputs (C32.1 R35.2)
CSO_IN22: TIDA-01237_MSDI_Main (U2.11), TIDA-01237_MSDI_Resistor_Coded_Inputs (C33.1 R36.2)
CSO_IN23: TIDA-01237_MSDI_Main (U2.12), TIDA-01237_MSDI_Resistor_Coded_Inputs (C34.1 R37.2 R38.2 R39.2)

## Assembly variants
001: not fitted FID1 FID2 FID3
